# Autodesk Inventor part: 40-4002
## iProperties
Created: 2005-05
Part Number: 40-4002
Document SubType Name: Modeling
Designer: tfa
Manufacturer: Standard
Standards Organization: Custom
Author: tfa
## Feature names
1. Basis1
